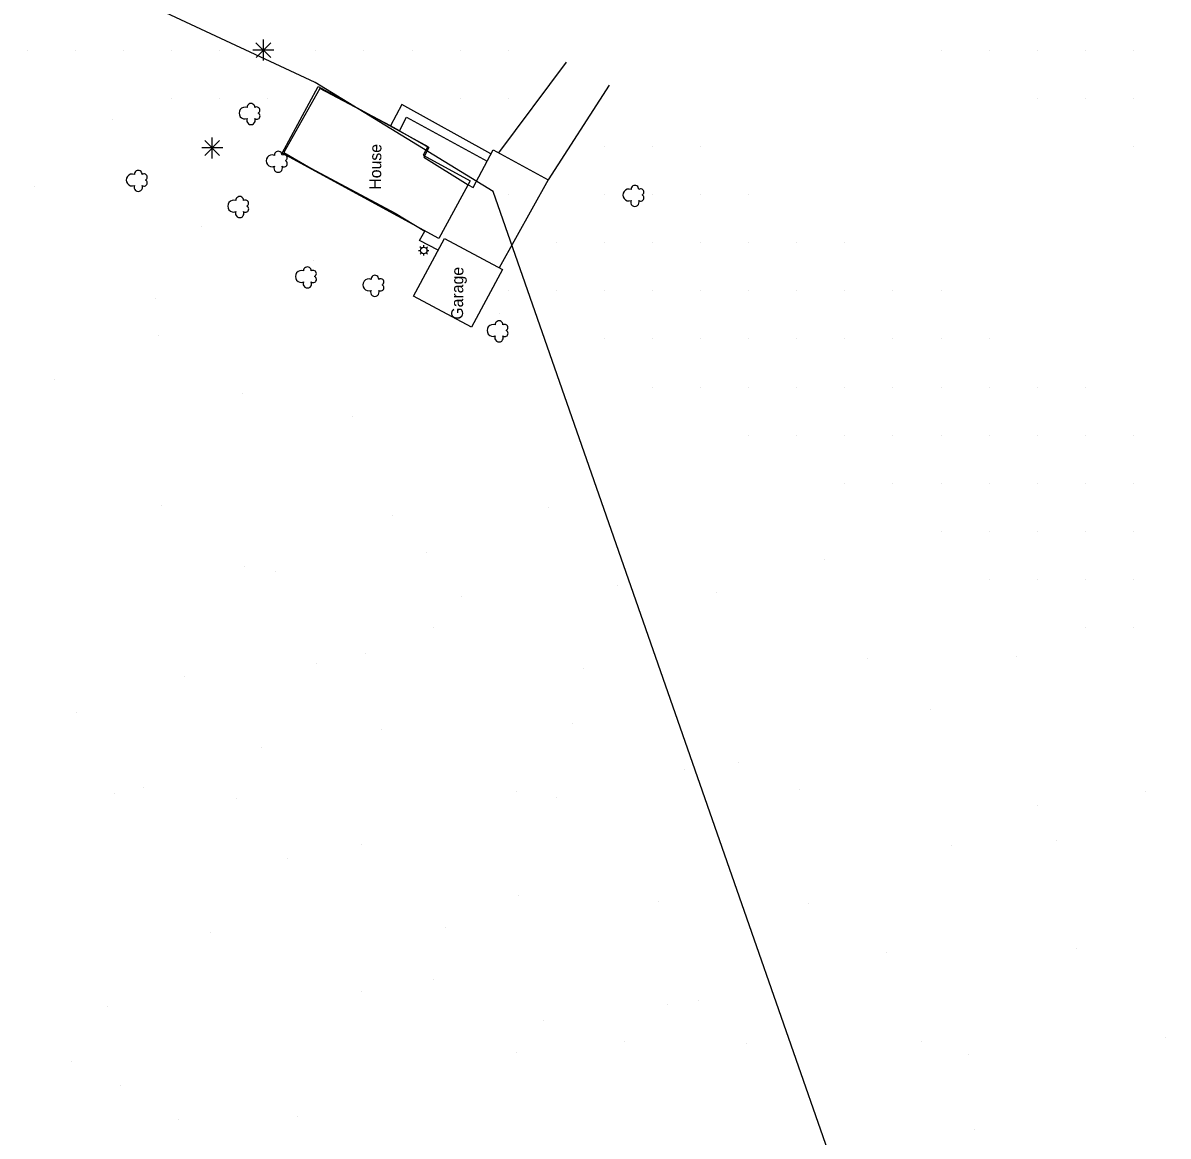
# Model space of a CAD drawing. Extents: x 19528164 to 19545171, y 7585743 to 7602745.
# Drawn here: x 19541918.2 to 19542394.4, y 7598453.5 to 7598916.5 of the extents above; entities that cross this region are included whole.
import ezdxf

# ---------------------------------------------------------------- set-up
doc = ezdxf.new("R2010")
doc.units = 0
for name, color, linetype in [('PhoBreakLine', 7, 'Continuous'), ('PhoBuilding', 7, 'Continuous'), ('PhoEdgeEntrancePaved', 7, 'Continuous'), ('PhoEdgeSidewalk', 7, 'Continuous'), ('PhoISAEPoints', 7, 'Continuous'), ('PhoNotesDesign', 7, 'Continuous'), ('PhoSurveyLimits', 7, 'Continuous'), ('PhoVegetation', 7, 'Continuous'), ('SurBreakLine', 7, 'Continuous'), ('SurEdgeEntranceUnpaved', 7, 'Continuous'), ('SurNaturalCells', 7, 'Continuous'), ('SurROWRail', 7, 'Continuous')]:
    doc.layers.add(name, color=color, linetype=linetype)

msp = doc.modelspace()

# ---------------------------------------------------------------- linework, layer by layer
at = {"layer": 'PhoBreakLine'}
for points in [[(19542074.74, 7598871.56), (19542070.98, 7598873.61), (19542041.64, 7598889.2), (19542026.66, 7598862.53), (19542037.96, 7598856.02), (19542072.99, 7598837.28), (19542085.34, 7598829.88)], [(19542074.74, 7598871.56), (19542087, 7598864.66), (19542084.94, 7598860.59), (19542103.3, 7598849.17)]]:
    msp.add_lwpolyline(points, dxfattribs=at)
at = {"layer": 'PhoBuilding'}
for points in [[(19542091.06, 7598826.75), (19542025.91, 7598862.31), (19542041, 7598889.97), (19542086.61, 7598865.08), (19542084.59, 7598861.4), (19542104.15, 7598850.72)], [(19542080.63, 7598802.76), (19542093.43, 7598826.75), (19542117.54, 7598813.89), (19542104.74, 7598789.9)]]:
    msp.add_lwpolyline(points, close=True, dxfattribs=at)
at = {"layer": 'PhoEdgeEntrancePaved'}
for points in [[(19542103.3, 7598849.17), (19542105.44, 7598847.99), (19542113.7, 7598863.71), (19542136.6, 7598851.13), (19542116.28, 7598814.57)], [(19542090.83, 7598821.88), (19542083.14, 7598825.96), (19542085.34, 7598829.88)]]:
    msp.add_lwpolyline(points, dxfattribs=at)
at = {"layer": 'PhoEdgeSidewalk'}
for points in [[(19542112.81, 7598862.02), (19542075.72, 7598882.55), (19542070.98, 7598873.61)], [(19542074.74, 7598871.56), (19542077.74, 7598877.3), (19542111.23, 7598859.01)]]:
    msp.add_lwpolyline(points, dxfattribs=at)
at = {"layer": 'PhoISAEPoints'}
for p, q in [((19541920, 7598905), (19541920, 7598905)), ((19541940, 7598905), (19541940, 7598905)), ((19541960, 7598905), (19541960, 7598905)), ((19541980, 7598905), (19541980, 7598905)), ((19542000, 7598905), (19542000, 7598905)), ((19542020, 7598905), (19542020, 7598905)), ((19542040, 7598905), (19542040, 7598905)), ((19542060, 7598905), (19542060, 7598905)), ((19542080, 7598905), (19542080, 7598905)), ((19542100, 7598905), (19542100, 7598905)), ((19542120, 7598905), (19542120, 7598905)), ((19542300, 7598905), (19542300, 7598905)), ((19542320, 7598905), (19542320, 7598905)), ((19542340, 7598905), (19542340, 7598905)), ((19542360, 7598905), (19542360, 7598905)), ((19542380, 7598905), (19542380, 7598905)), ((19541980, 7598885), (19541980, 7598885)), ((19542000, 7598885), (19542000, 7598885)), ((19542020, 7598885), (19542020, 7598885)), ((19542100, 7598885), (19542100, 7598885)), ((19542120, 7598885), (19542120, 7598885)), ((19542340, 7598885), (19542340, 7598885)), ((19542360, 7598885), (19542360, 7598885)), ((19542380, 7598885), (19542380, 7598885)), ((19542160, 7598865), (19542160, 7598865)), ((19542180, 7598865), (19542180, 7598865)), ((19542200, 7598865), (19542200, 7598865)), ((19542380, 7598865), (19542380, 7598865)), ((19542120, 7598845), (19542120, 7598845)), ((19542160, 7598845), (19542160, 7598845)), ((19542180, 7598845), (19542180, 7598845)), ((19542200, 7598845), (19542200, 7598845)), ((19542220, 7598845), (19542220, 7598845)), ((19542140, 7598825), (19542140, 7598825)), ((19542160, 7598825), (19542160, 7598825)), ((19542180, 7598825), (19542180, 7598825)), ((19542200, 7598825), (19542200, 7598825)), ((19542220, 7598825), (19542220, 7598825)), ((19542240, 7598825), (19542240, 7598825)), ((19542260, 7598825), (19542260, 7598825)), ((19542120, 7598805), (19542120, 7598805)), ((19542140, 7598805), (19542140, 7598805)), ((19542160, 7598805), (19542160, 7598805)), ((19542180, 7598805), (19542180, 7598805)), ((19542200, 7598805), (19542200, 7598805)), ((19542220, 7598805), (19542220, 7598805)), ((19542240, 7598805), (19542240, 7598805)), ((19542260, 7598805), (19542260, 7598805)), ((19542280, 7598805), (19542280, 7598805)), ((19542300, 7598805), (19542300, 7598805)), ((19542160, 7598785), (19542160, 7598785)), ((19542180, 7598785), (19542180, 7598785)), ((19542200, 7598785), (19542200, 7598785)), ((19542220, 7598785), (19542220, 7598785)), ((19542240, 7598785), (19542240, 7598785)), ((19542260, 7598785), (19542260, 7598785)), ((19542280, 7598785), (19542280, 7598785)), ((19542300, 7598785), (19542300, 7598785)), ((19542320, 7598785), (19542320, 7598785)), ((19542180, 7598765), (19542180, 7598765)), ((19542200, 7598765), (19542200, 7598765)), ((19542220, 7598765), (19542220, 7598765)), ((19542240, 7598765), (19542240, 7598765)), ((19542260, 7598765), (19542260, 7598765)), ((19542280, 7598765), (19542280, 7598765)), ((19542300, 7598765), (19542300, 7598765)), ((19542320, 7598765), (19542320, 7598765)), ((19542340, 7598765), (19542340, 7598765)), ((19542360, 7598765), (19542360, 7598765)), ((19542220, 7598745), (19542220, 7598745)), ((19542240, 7598745), (19542240, 7598745)), ((19542260, 7598745), (19542260, 7598745)), ((19542280, 7598745), (19542280, 7598745)), ((19542300, 7598745), (19542300, 7598745)), ((19542320, 7598745), (19542320, 7598745)), ((19542340, 7598745), (19542340, 7598745)), ((19542360, 7598745), (19542360, 7598745)), ((19542380, 7598745), (19542380, 7598745)), ((19542260, 7598725), (19542260, 7598725)), ((19542280, 7598725), (19542280, 7598725)), ((19542300, 7598725), (19542300, 7598725)), ((19542320, 7598725), (19542320, 7598725)), ((19542340, 7598725), (19542340, 7598725)), ((19542360, 7598725), (19542360, 7598725)), ((19542380, 7598725), (19542380, 7598725)), ((19542300, 7598705), (19542300, 7598705)), ((19542320, 7598705), (19542320, 7598705)), ((19542340, 7598705), (19542340, 7598705)), ((19542360, 7598705), (19542360, 7598705)), ((19542380, 7598705), (19542380, 7598705)), ((19542320, 7598685), (19542320, 7598685)), ((19542340, 7598685), (19542340, 7598685)), ((19542360, 7598685), (19542360, 7598685)), ((19542380, 7598685), (19542380, 7598685)), ((19542360, 7598665), (19542360, 7598665)), ((19542380, 7598665), (19542380, 7598665))]:
    msp.add_line(p, q, dxfattribs=at)
at = {"layer": 'PhoSurveyLimits'}
msp.add_lwpolyline([(19541832.46, 7597845.39), (19542376.97, 7598092.17), (19542113.78, 7598846.31), (19542039.74, 7598891.68), (19541786.93, 7599009.68), (19541786.81, 7599059.41), (19541708.63, 7599061.66), (19541440.61, 7599116.66), (19541458.99, 7599214.49), (19541802.13, 7599193.81), (19541861.6, 7599154.2), (19541900.69, 7599150.34), (19541983.87, 7599142.12), (19543859.55, 7599862.07), (19543863.55, 7599896.16), (19543904.76, 7600247.38), (19543914.92, 7600450.3), (19543927.42, 7600632.62), (19543934.84, 7600743.15), (19543933.97, 7600882.93)], dxfattribs=at)
at = {"layer": 'PhoVegetation'}
for p, q in [((19542021.28, 7598902.05), (19542015.09, 7598908.22)), ((19542021.27, 7598908.23), (19542015.1, 7598902.04)), ((19542018.19, 7598900.76), (19542018.18, 7598909.51)), ((19542022.56, 7598905.14), (19542013.81, 7598905.13)), ((19542018.19, 7598905.13), (19542018.19, 7598905.13)), ((19541996.87, 7598860.08), (19541996.87, 7598868.83)), ((19542001.24, 7598864.46), (19541992.5, 7598864.45)), ((19541999.97, 7598861.37), (19541993.77, 7598867.55)), ((19541999.96, 7598867.55), (19541993.78, 7598861.36)), ((19541996.87, 7598864.46), (19541996.87, 7598864.46))]:
    msp.add_line(p, q, dxfattribs=at)
for centre, radius, start, end in [((19542013.01, 7598881.35), 1.6, 356.0558, 184.0595), ((19542010.5, 7598878.95), 2.46, 68.2627, 291.8526), ((19542015.39, 7598880.15), 1.34, 296.5818, 125.461), ((19542015.43, 7598877.73), 1.34, 232.8078, 65.38), ((19542013.02, 7598875.93), 1.76, 155.54, 24.5752), ((19542021.81, 7598859.09), 2.46, 68.2627, 291.8526), ((19542024.32, 7598861.49), 1.6, 356.0558, 184.0595), ((19542026.7, 7598860.29), 1.34, 296.5818, 125.461), ((19542026.74, 7598857.88), 1.34, 232.8078, 65.38), ((19541966.12, 7598853.51), 1.6, 356.0558, 184.0595), ((19542024.33, 7598856.08), 1.76, 155.54, 24.5752), ((19541963.61, 7598851.11), 2.46, 68.2627, 291.8526), ((19541968.5, 7598852.31), 1.34, 296.5818, 125.461), ((19541968.54, 7598849.9), 1.34, 232.8078, 65.38), ((19541966.13, 7598848.1), 1.76, 155.54, 24.5752), ((19542170.14, 7598844.88), 2.46, 68.2627, 291.8526), ((19542172.65, 7598847.28), 1.6, 356.0558, 184.0595), ((19542175.03, 7598846.08), 1.34, 296.5818, 125.461), ((19542175.07, 7598843.67), 1.34, 232.8078, 65.38), ((19542005.81, 7598840.25), 2.46, 68.2627, 291.8526), ((19542008.32, 7598842.65), 1.6, 356.0558, 184.0595), ((19542010.7, 7598841.45), 1.34, 296.5818, 125.461), ((19542010.74, 7598839.04), 1.34, 232.8078, 65.38), ((19542172.66, 7598841.87), 1.76, 155.54, 24.5752), ((19542008.33, 7598837.24), 1.76, 155.54, 24.5752), ((19542033.96, 7598810.99), 2.46, 68.2627, 291.8526), ((19542036.47, 7598813.39), 1.6, 356.0558, 184.0595), ((19542038.85, 7598812.19), 1.34, 296.5818, 125.461), ((19542038.89, 7598809.78), 1.34, 232.8078, 65.38), ((19542064.52, 7598809.9), 1.6, 356.0558, 184.0595), ((19542036.48, 7598807.98), 1.76, 155.54, 24.5752), ((19542062.01, 7598807.5), 2.46, 68.2627, 291.8526), ((19542066.9, 7598808.7), 1.34, 296.5818, 125.461), ((19542066.94, 7598806.29), 1.34, 232.8078, 65.38), ((19542064.53, 7598804.49), 1.76, 155.54, 24.5752), ((19542116.17, 7598790.95), 1.6, 356.0558, 184.0595), ((19542113.65, 7598788.55), 2.46, 68.2627, 291.8526), ((19542118.54, 7598789.75), 1.34, 296.5818, 125.461), ((19542118.58, 7598787.33), 1.34, 232.8078, 65.38), ((19542116.17, 7598785.53), 1.76, 155.54, 24.5752)]:
    msp.add_arc(centre, radius, start, end, dxfattribs=at)
at = {"layer": 'SurBreakLine'}
for points in [[(19542074.74, 7598871.56), (19542070.98, 7598873.61), (19542041.64, 7598889.2), (19542026.66, 7598862.53), (19542037.96, 7598856.02), (19542072.99, 7598837.28), (19542085.34, 7598829.88)], [(19542112.81, 7598862.02), (19542075.72, 7598882.55), (19542070.98, 7598873.61)], [(19542074.74, 7598871.56), (19542077.74, 7598877.3), (19542111.23, 7598859.01)], [(19542074.74, 7598871.56), (19542087, 7598864.66), (19542084.94, 7598860.59), (19542103.3, 7598849.17)], [(19542103.3, 7598849.17), (19542105.44, 7598847.99), (19542113.7, 7598863.71), (19542136.6, 7598851.13), (19542116.28, 7598814.57)], [(19542090.83, 7598821.88), (19542083.14, 7598825.96), (19542085.34, 7598829.88)]]:
    msp.add_lwpolyline(points, dxfattribs=at)
at = {"layer": 'SurEdgeEntranceUnpaved'}
for p, q in [((19541920, 7598905), (19541920, 7598905)), ((19541940, 7598905), (19541940, 7598905)), ((19541960, 7598905), (19541960, 7598905)), ((19541980, 7598905), (19541980, 7598905)), ((19542000, 7598905), (19542000, 7598905)), ((19541980, 7598885), (19541980, 7598885)), ((19542000, 7598885), (19542000, 7598885)), ((19542020, 7598885), (19542020, 7598885)), ((19541955.26, 7598876.17), (19541955.26, 7598876.17)), ((19541922.8, 7598848.37), (19541922.8, 7598848.37)), ((19542120, 7598845), (19542120, 7598845)), ((19541992.42, 7598831.61), (19541992.42, 7598831.61)), ((19542140, 7598825), (19542140, 7598825)), ((19542160, 7598825), (19542160, 7598825)), ((19542039.16, 7598817.5), (19542039.16, 7598817.5)), ((19541973.09, 7598802.02), (19541973.09, 7598802.02)), ((19542120, 7598805), (19542120, 7598805)), ((19542140, 7598805), (19542140, 7598805)), ((19542160, 7598805), (19542160, 7598805)), ((19542180, 7598805), (19542180, 7598805)), ((19542116.28, 7598795.61), (19542116.28, 7598795.61)), ((19541974.66, 7598786.32), (19541974.66, 7598786.32)), ((19542160, 7598785), (19542160, 7598785)), ((19542180, 7598785), (19542180, 7598785)), ((19542200, 7598785), (19542200, 7598785)), ((19542220, 7598785), (19542220, 7598785)), ((19541931.36, 7598768.17), (19541931.36, 7598768.17)), ((19542180, 7598765), (19542180, 7598765)), ((19542200, 7598765), (19542200, 7598765)), ((19542220, 7598765), (19542220, 7598765)), ((19542240, 7598765), (19542240, 7598765)), ((19542009.3, 7598762.36), (19542009.3, 7598762.36)), ((19542055.23, 7598752.71), (19542055.23, 7598752.71)), ((19542220, 7598745), (19542220, 7598745)), ((19542240, 7598745), (19542240, 7598745)), ((19542260, 7598745), (19542260, 7598745)), ((19542280, 7598745), (19542280, 7598745)), ((19542260, 7598725), (19542260, 7598725)), ((19542280, 7598725), (19542280, 7598725)), ((19542300, 7598725), (19542300, 7598725)), ((19541975.73, 7598715.75), (19541975.73, 7598715.75)), ((19542071.89, 7598711.45), (19542071.89, 7598711.45)), ((19542136.78, 7598714.89), (19542136.78, 7598714.89)), ((19542300, 7598705), (19542300, 7598705)), ((19542320, 7598705), (19542320, 7598705)), ((19542340, 7598705), (19542340, 7598705)), ((19542086.2, 7598696.35), (19542086.2, 7598696.35)), ((19542251.39, 7598693.43), (19542251.39, 7598693.43)), ((19542010.14, 7598690.21), (19542010.14, 7598690.21)), ((19542023.36, 7598688.15), (19542023.36, 7598688.15)), ((19542165.24, 7598682.47), (19542165.24, 7598682.47)), ((19542320, 7598685), (19542320, 7598685)), ((19542340, 7598685), (19542340, 7598685)), ((19542360, 7598685), (19542360, 7598685)), ((19542100.67, 7598677.84), (19542100.67, 7598677.84)), ((19542206.45, 7598679.36), (19542206.45, 7598679.36)), ((19542089.02, 7598664.87), (19542089.02, 7598664.87)), ((19542360, 7598665), (19542360, 7598665)), ((19542380, 7598665), (19542380, 7598665)), ((19542060.77, 7598654.33), (19542060.77, 7598654.33)), ((19542040.12, 7598649.94), (19542040.12, 7598649.94)), ((19542269.48, 7598652.25), (19542269.48, 7598652.25)), ((19542331.48, 7598652.84), (19542331.48, 7598652.84)), ((19541985.36, 7598644.61), (19541985.36, 7598644.61)), ((19542151.25, 7598648.03), (19542151.25, 7598648.03)), ((19542295.63, 7598631.09), (19542295.63, 7598631.09)), ((19541940.33, 7598629.8), (19541940.33, 7598629.8)), ((19542146.6, 7598625.2), (19542146.6, 7598625.2)), ((19542067.17, 7598622.51), (19542067.17, 7598622.51)), ((19542017.53, 7598615.13), (19542017.53, 7598615.13)), ((19542215.79, 7598608.97), (19542215.79, 7598608.97)), ((19542193.37, 7598605.96), (19542193.37, 7598605.96)), ((19541968.39, 7598598.56), (19541968.39, 7598598.56)), ((19542123.37, 7598596.99), (19542123.37, 7598596.99)), ((19542240.94, 7598597.53), (19542240.94, 7598597.53)), ((19542385, 7598596.99), (19542385, 7598596.99)), ((19541956.37, 7598595.86), (19541956.37, 7598595.86)), ((19542006.95, 7598593.98), (19542006.95, 7598593.98)), ((19542140.17, 7598594.2), (19542140.17, 7598594.2)), ((19542339.89, 7598590.82), (19542339.89, 7598590.82)), ((19542059.09, 7598574.9), (19542059.09, 7598574.9)), ((19542304.24, 7598574.22), (19542304.24, 7598574.22)), ((19542348.09, 7598576.49), (19542348.09, 7598576.49)), ((19542028.19, 7598569.03), (19542028.19, 7598569.03)), ((19542124.3, 7598553.43), (19542124.3, 7598553.43)), ((19542182.65, 7598551.04), (19542182.65, 7598551.04)), ((19542244.85, 7598550.22), (19542244.85, 7598550.22)), ((19542093.94, 7598540.43), (19542093.94, 7598540.43)), ((19541996.06, 7598538.01), (19541996.06, 7598538.01)), ((19542277.1, 7598530.03), (19542277.1, 7598530.03)), ((19542356.2, 7598531.61), (19542356.2, 7598531.61)), ((19542089.07, 7598518.55), (19542089.07, 7598518.55)), ((19542058.77, 7598513.62), (19542058.77, 7598513.62)), ((19541953.46, 7598507.18), (19541953.46, 7598507.18)), ((19542186.3, 7598508.27), (19542186.3, 7598508.27)), ((19542199.14, 7598509.91), (19542199.14, 7598509.91)), ((19542134.63, 7598501.71), (19542134.63, 7598501.71)), ((19542168.18, 7598492.91), (19542168.18, 7598492.91)), ((19542219.02, 7598492.15), (19542219.02, 7598492.15)), ((19542291.92, 7598492.68), (19542291.92, 7598492.68)), ((19542393.15, 7598494.54), (19542393.15, 7598494.54)), ((19542123.31, 7598488.22), (19542123.31, 7598488.22)), ((19542311.24, 7598487.59), (19542311.24, 7598487.59)), ((19541938.31, 7598484.34), (19541938.31, 7598484.34)), ((19541958.58, 7598474.55), (19541958.58, 7598474.55)), ((19541982.7, 7598460.48), (19541982.7, 7598460.48)), ((19542032.33, 7598461.59), (19542032.33, 7598461.59)), ((19542313.8, 7598456.07), (19542313.8, 7598456.07))]:
    msp.add_line(p, q, dxfattribs=at)
at = {"layer": 'SurNaturalCells'}
for p, q in [((19542082.66, 7598821.83), (19542083.47, 7598821.83)), ((19542083.87, 7598822.79), (19542083.29, 7598823.37)), ((19542083.3, 7598820.29), (19542083.87, 7598820.87)), ((19542084.83, 7598823.19), (19542084.83, 7598824.01)), ((19542084.84, 7598819.66), (19542084.84, 7598820.47)), ((19542085.79, 7598822.79), (19542086.37, 7598823.37)), ((19542086.37, 7598820.3), (19542085.8, 7598820.87)), ((19542086.19, 7598821.83), (19542087.01, 7598821.83))]:
    msp.add_line(p, q, dxfattribs=at)
msp.add_circle((19542084.83, 7598821.83), 1.36, dxfattribs=at)
at = {"layer": 'SurROWRail'}
for p, q in [((19542144.06, 7598900.12), (19542115.98, 7598862.46)), ((19542161.97, 7598890.55), (19542136.6, 7598851.13))]:
    msp.add_line(p, q, dxfattribs=at)

# ---------------------------------------------------------------- texts
at = {"layer": 'PhoNotesDesign'}
for s, p in [('House', (19542067.11, 7598847.07)), ('Garage', (19542101.18, 7598793.02))]:
    msp.add_text(s, height=4.92, rotation=89.5617, dxfattribs=at).set_placement(p)

doc.saveas('drawing.dxf')
